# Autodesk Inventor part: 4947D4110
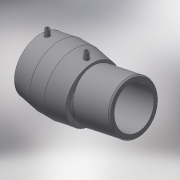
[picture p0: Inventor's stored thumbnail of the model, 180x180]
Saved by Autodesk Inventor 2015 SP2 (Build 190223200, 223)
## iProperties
Created: 2017-06
Part Number: 4947D4110
Material: Generic
Description: PLASSON ADJUSTABLE ELBOW (ONE SIDE) 110
Document SubType Name: Modeling
Designer: KIM
Mass: 1379.77 g
Surface Area: 2113.98 cm^2
Volume: 1379.77 cm^3
Density: 1 g/cm^3
Appearance: Default
Author: KIM
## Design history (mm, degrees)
derived "4947D4.ipt"
feature "Solid1::4947D4.ipt"
tag "TaggingFeature1"
body "Solid1"
other parameters: "d0" = 144.9, "d3" = 85, "d4" = 42.5, "d5" = 126, "d8" = 168 deg, "d10" = 34, "d11" = 11.33333, "d29" = 83, "d30" = 15, "d31" = 55.2, "d34" = 5 deg, "d41" = 4, "d42" = 14, "d43" = 0, "d48" = 99, "d55" = 35.94, "d57" = 168 deg, "d62" = 3, "d63" = 0, "d65" = 276, "d67" = 99, "d68" = 135 deg, "d69" = 85, "d70" = 51.8, "d71" = 2.8, "L_" = 276, "L_1" = 85, "A_" = 83, "d_2" = 12, "L_0" = 148, "L_2" = 85, "d54" = 59.9, "d59" = 167.78449
